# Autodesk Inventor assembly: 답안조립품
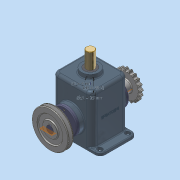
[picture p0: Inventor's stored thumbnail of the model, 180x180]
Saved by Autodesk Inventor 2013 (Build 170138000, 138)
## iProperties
Created: 2015-01
Part Number: 답안조립품
Document SubType Name: Assembly
Designer: WINDOWS7
Mass: 6474.97 g
Surface Area: 4424.07 cm^2
Volume: 1987.46 cm^3
Density: 3.25791 g/cm^3
Author: WINDOWS7
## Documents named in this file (15)
- C:\Users\WINDOWS7\Desktop\350106V1033\답안조립품.iam
- C:\Users\WINDOWS7\Desktop\350106V1033\본체.ipt
- C:\Users\WINDOWS7\Desktop\350106V1033\커버.ipt
- C:\Users\WINDOWS7\Desktop\350106V1033\베어링 6205.ipt
- C:\Users\WINDOWS7\Desktop\350106V1033\오일실.ipt
- C:\Users\WINDOWS7\Desktop\350106V1033\M4x0.5.ipt
- C:\Users\WINDOWS7\Desktop\350106V1033\부시.ipt
- C:\Users\WINDOWS7\Desktop\350106V1033\편심축.ipt
- C:\Users\WINDOWS7\Desktop\350106V1033\멈춤링.ipt
- C:\Users\WINDOWS7\Desktop\350106V1033\키 8x8.ipt
- C:\Users\WINDOWS7\Desktop\350106V1033\V-벨트풀리.ipt
- C:\Users\WINDOWS7\Desktop\350106V1033\체인 스프로킷.ipt
- C:\Users\WINDOWS7\Desktop\350106V1033\멈춤나사 M5x0.5.ipt
- C:\Users\WINDOWS7\Desktop\350106V1033\슬라이드.ipt
- C:\Users\WINDOWS7\Desktop\350106V1033\7-가변스프링.ipt
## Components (9 placed, 4 different names)
1. V-벨트풀리:1
2. 5-체인 스프로킷:1
3. 7-가변스프링:1
4. M4x0.5:1
5. M4x0.5:3
6. M4x0.5:4
7. M4x0.5:2
8. M4x0.5:5
9. M4x0.5:6
